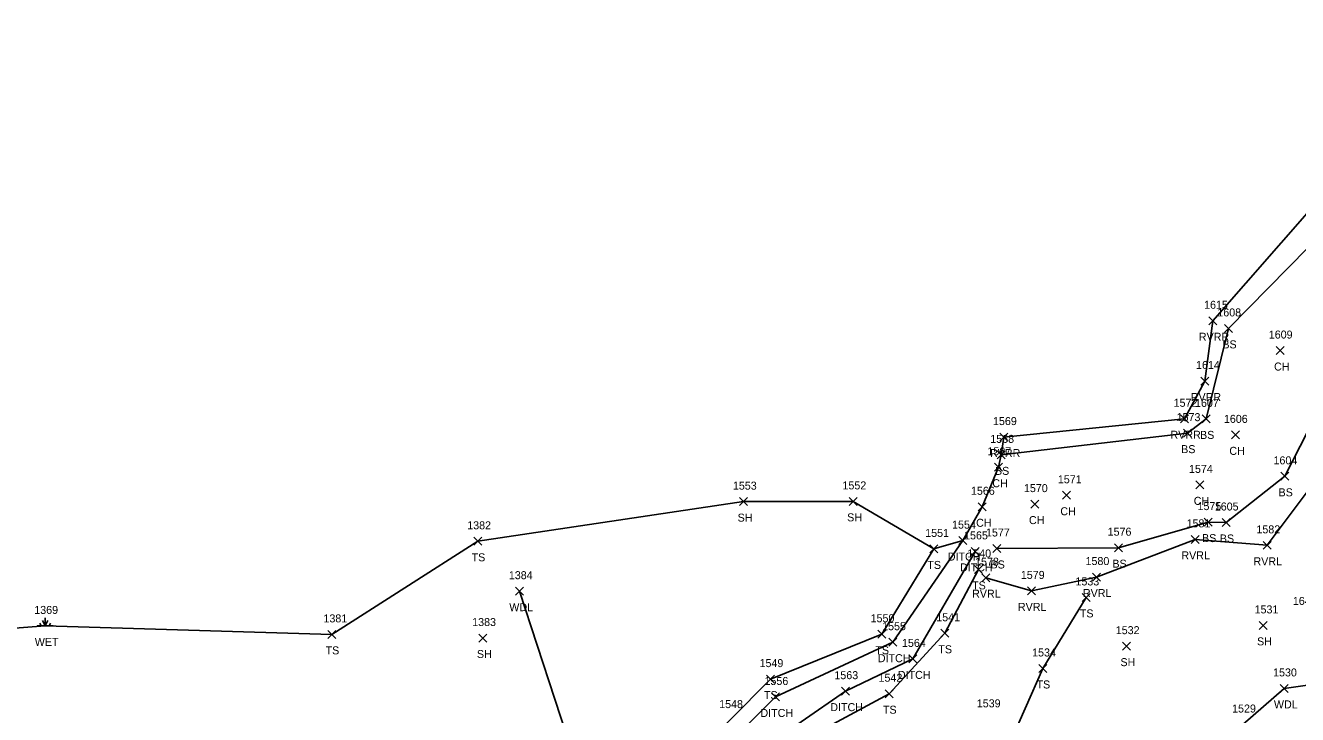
# Model space of a CAD drawing. Extents: x 1633660 to 1636532, y 388643 to 392631.
# Drawn here: x 1633906 to 1634224, y 388875.9 to 389048.3 of the extents above; entities that cross this region are included whole.
import ezdxf

# ---------------------------------------------------------------- set-up
doc = ezdxf.new("R2010")
doc.units = 0
for name, color, linetype in [('D_A', 7, 'Continuous'), ('D_I', 7, 'Continuous'), ('D_TIC', 7, 'Continuous'), ('DD', 7, 'Continuous'), ('L_A', 7, 'Continuous'), ('L_I', 7, 'Continuous'), ('L_TIC', 7, 'Continuous'), ('LAWA', 7, 'Continuous'), ('LAWE', 7, 'Continuous'), ('LELB', 7, 'Continuous'), ('LSOGP', 7, 'Continuous'), ('LWET', 7, 'Continuous')]:
    doc.layers.add(name, color=color, linetype=linetype)

msp = doc.modelspace()

# ---------------------------------------------------------------- linework, layer by layer
at = {"layer": 'D_TIC'}
for points in [[(1634139.31, 388918.4), (1634141.31, 388920.4)], [(1634141.31, 388918.4), (1634139.31, 388920.4)], [(1634142.36, 388915.71), (1634144.36, 388917.71)], [(1634144.36, 388915.71), (1634142.36, 388917.71)], [(1634121.83, 388892.99), (1634123.83, 388894.99)], [(1634123.83, 388892.99), (1634121.83, 388894.99)], [(1634126.84, 388888.81), (1634128.84, 388890.81)], [(1634128.84, 388888.81), (1634126.84, 388890.81)], [(1634109.94, 388880.74), (1634111.94, 388882.74)], [(1634111.94, 388880.74), (1634109.94, 388882.74)], [(1634092.48, 388879.29), (1634094.48, 388881.29)], [(1634094.48, 388879.29), (1634092.48, 388881.29)]]:
    msp.add_lwpolyline(points, dxfattribs=at)
at = {"layer": 'DD'}
msp.add_lwpolyline([(1634140.31, 388919.4), (1634122.83, 388893.99), (1634093.48, 388880.29), (1634083.12, 388870.01), (1634069.93, 388859.42), (1634050.51, 388859.37), (1634048.14, 388856.2), (1634070.58, 388854.91), (1634088.81, 388866.37), (1634110.94, 388881.74), (1634127.84, 388889.81), (1634143.36, 388916.71)], dxfattribs=at)
at = {"layer": 'L_TIC'}
for points in [[(1634201.79, 388973.39), (1634203.79, 388975.39)], [(1634203.79, 388973.39), (1634201.79, 388975.39)], [(1634205.75, 388971.48), (1634207.75, 388973.48)], [(1634207.75, 388971.48), (1634205.75, 388973.48)], [(1634218.62, 388965.94), (1634220.62, 388967.94)], [(1634220.62, 388965.94), (1634218.62, 388967.94)], [(1634199.78, 388958.32), (1634201.78, 388960.32)], [(1634201.78, 388958.32), (1634199.78, 388960.32)], [(1634194.7, 388948.88), (1634196.7, 388950.88)], [(1634196.7, 388948.88), (1634194.7, 388950.88)], [(1634200.17, 388948.84), (1634202.17, 388950.84)], [(1634202.17, 388948.84), (1634200.17, 388950.84)], [(1634149.59, 388944.3), (1634151.59, 388946.3)], [(1634151.59, 388944.3), (1634149.59, 388946.3)], [(1634195.44, 388945.28), (1634197.44, 388947.28)], [(1634197.44, 388945.28), (1634195.44, 388947.28)], [(1634207.44, 388944.85), (1634209.44, 388946.85)], [(1634209.44, 388944.85), (1634207.44, 388946.85)], [(1634148.91, 388939.85), (1634150.91, 388941.85)], [(1634150.91, 388939.85), (1634148.91, 388941.85)], [(1634148.19, 388936.75), (1634150.19, 388938.75)], [(1634150.19, 388936.75), (1634148.19, 388938.75)], [(1634219.78, 388934.48), (1634221.78, 388936.48)], [(1634221.78, 388934.48), (1634219.78, 388936.48)], [(1634198.55, 388932.34), (1634200.55, 388934.34)], [(1634200.55, 388932.34), (1634198.55, 388934.34)], [(1634084.52, 388928.15), (1634086.52, 388930.15)], [(1634086.52, 388928.15), (1634084.52, 388930.15)], [(1634111.91, 388928.21), (1634113.91, 388930.21)], [(1634113.91, 388928.21), (1634111.91, 388930.21)], [(1634165.19, 388929.74), (1634167.19, 388931.74)], [(1634167.19, 388929.74), (1634165.19, 388931.74)], [(1634144.14, 388926.86), (1634146.14, 388928.86)], [(1634146.14, 388926.86), (1634144.14, 388928.86)], [(1634157.35, 388927.53), (1634159.35, 388929.53)], [(1634159.35, 388927.53), (1634157.35, 388929.53)], [(1634200.67, 388923.03), (1634202.67, 388925.03)], [(1634202.67, 388923.03), (1634200.67, 388925.03)], [(1634205.11, 388922.93), (1634207.11, 388924.93)], [(1634207.11, 388922.93), (1634205.11, 388924.93)], [(1634197.37, 388918.71), (1634199.37, 388920.71)], [(1634199.37, 388918.71), (1634197.37, 388920.71)], [(1634018.11, 388918.23), (1634020.11, 388920.23)], [(1634020.11, 388918.23), (1634018.11, 388920.23)], [(1634132.03, 388916.32), (1634134.03, 388918.32)], [(1634134.03, 388916.32), (1634132.03, 388918.32)], [(1634147.79, 388916.43), (1634149.79, 388918.43)], [(1634149.79, 388916.43), (1634147.79, 388918.43)], [(1634178.26, 388916.63), (1634180.26, 388918.63)], [(1634180.26, 388916.63), (1634178.26, 388918.63)], [(1634215.39, 388917.22), (1634217.39, 388919.22)], [(1634217.39, 388917.22), (1634215.39, 388919.22)], [(1634143.21, 388911.2), (1634145.21, 388913.2)], [(1634145.21, 388911.2), (1634143.21, 388913.2)], [(1634145.07, 388909.13), (1634147.07, 388911.13)], [(1634147.07, 388909.13), (1634145.07, 388911.13)], [(1634172.76, 388909.29), (1634174.76, 388911.29)], [(1634174.76, 388909.29), (1634172.76, 388911.29)], [(1634028.51, 388905.75), (1634030.51, 388907.75)], [(1634030.51, 388905.75), (1634028.51, 388907.75)], [(1634156.51, 388905.82), (1634158.51, 388907.82)], [(1634158.51, 388905.82), (1634156.51, 388907.82)], [(1634170.15, 388904.19), (1634172.15, 388906.19)], [(1634172.15, 388904.19), (1634170.15, 388906.19)], [(1634214.37, 388897.19), (1634216.37, 388899.19)], [(1634216.37, 388897.19), (1634214.37, 388899.19)], [(1633981.61, 388894.94), (1633983.61, 388896.94)], [(1633983.61, 388894.94), (1633981.61, 388896.94)], [(1634019.35, 388894.03), (1634021.35, 388896.03)], [(1634021.35, 388894.03), (1634019.35, 388896.03)], [(1634119.03, 388894.98), (1634121.03, 388896.98)], [(1634121.03, 388894.98), (1634119.03, 388896.98)], [(1634134.78, 388895.22), (1634136.78, 388897.22)], [(1634136.78, 388895.22), (1634134.78, 388897.22)], [(1634180.23, 388892), (1634182.23, 388894)], [(1634182.23, 388892), (1634180.23, 388894)], [(1634091.19, 388883.76), (1634093.19, 388885.76)], [(1634093.19, 388883.76), (1634091.19, 388885.76)], [(1634159.33, 388886.42), (1634161.33, 388888.42)], [(1634161.33, 388886.42), (1634159.33, 388888.42)], [(1634219.65, 388881.43), (1634221.65, 388883.43)], [(1634221.65, 388881.43), (1634219.65, 388883.43)], [(1634120.93, 388880.1), (1634122.93, 388882.1)], [(1634122.93, 388880.1), (1634120.93, 388882.1)]]:
    msp.add_lwpolyline(points, dxfattribs=at)
at = {"layer": 'LAWA'}
msp.add_lwpolyline([(1634029.51, 388906.75), (1634042.75, 388866.2), (1634043.29, 388851.86), (1634059.73, 388819.64), (1634086.07, 388831.91), (1634132.5, 388845.49), (1634141.64, 388844.49), (1634171.78, 388858.91), (1634210.32, 388873.4), (1634220.65, 388882.43), (1634241.67, 388885.4), (1634275.37, 388895.77), (1634312.68, 388911.32), (1634346.59, 388927.34), (1634362.7, 388937.8), (1634391.49, 388949.24), (1634419.55, 388956.24), (1634431.93, 388958.02)], dxfattribs=at)
at = {"layer": 'LAWE'}
for points in [[(1634150.59, 388945.3), (1634195.7, 388949.88), (1634200.78, 388959.32), (1634202.79, 388974.39), (1634228.12, 389003.28), (1634254.18, 389019.53), (1634275.87, 389031.31), (1634293.32, 389038.19), (1634304.06, 389038.64), (1634325.39, 389043.75), (1634351.31, 389048.27), (1634372.94, 389046.82), (1634401.07, 389040.69), (1634429.33, 389021.76), (1634441.52, 388999.11), (1634453.12, 388983.42), (1634462.64, 388983.3)], [(1634146.07, 388910.13), (1634157.51, 388906.82), (1634173.76, 388910.29), (1634198.37, 388919.71), (1634216.39, 388918.22), (1634229.12, 388935.26), (1634227.8, 388943.9), (1634246.12, 388965.87), (1634248.24, 388978.32), (1634283.08, 388994.35), (1634319.09, 389007.07), (1634380.98, 389013.99), (1634391.62, 389015.99), (1634409.17, 388992.61), (1634421.79, 388970.69), (1634427.66, 388965.96), (1634434.35, 388960.52)]]:
    msp.add_lwpolyline(points, dxfattribs=at)
at = {"layer": 'LELB'}
for points in [[(1634201.17, 388949.84), (1634206.75, 388972.48), (1634226.62, 388992.7), (1634256.26, 389010.51), (1634290.54, 389028.45), (1634305.7, 389035.69)], [(1634309.1, 389009.74), (1634284.02, 388998.65), (1634245.57, 388982.01), (1634241.27, 388965.71), (1634230.47, 388954.47), (1634220.78, 388935.48), (1634206.11, 388923.93)], [(1634201.17, 388949.84), (1634196.44, 388946.28)], [(1634149.91, 388940.85), (1634196.44, 388946.28)], [(1634201.67, 388924.03), (1634179.26, 388917.63), (1634148.79, 388917.43)], [(1634201.67, 388924.03), (1634206.11, 388923.93)], [(1633982.61, 388895.94), (1634019.11, 388919.23)], [(1634144.21, 388912.2), (1634135.78, 388896.22), (1634121.93, 388881.1), (1634093.91, 388866), (1634071.27, 388853.48), (1634044.09, 388851.99), (1634045.65, 388862.67), (1634068.75, 388861.41), (1634082.09, 388874.51), (1634092.19, 388884.76), (1634120.03, 388895.98), (1634133.03, 388917.32)], [(1634171.15, 388905.19), (1634160.33, 388887.42), (1634151.47, 388867.44), (1634142.01, 388846.15)]]:
    msp.add_lwpolyline(points, dxfattribs=at)
at = {"layer": 'LSOGP'}
msp.add_lwpolyline([(1634228.12, 389003.28), (1634202.79, 388974.39), (1634200.78, 388959.32), (1634195.7, 388949.88), (1634150.59, 388945.3), (1634149.91, 388940.85), (1634149.19, 388937.75), (1634145.14, 388927.86), (1634140.31, 388919.4), (1634133.03, 388917.32), (1634112.91, 388929.21), (1634085.52, 388929.15), (1634019.11, 388919.23), (1633982.61, 388895.94), (1633910.94, 388898.06), (1633887.99, 388896.34)], dxfattribs=at)
at = {"layer": 'LWET'}
for p, q in [((1633909.94, 388898.06), (1633909.61, 388898.73)), ((1633910.94, 388898.06), (1633910.28, 388899.39)), ((1633910.94, 388898.06), (1633910.94, 388900.06)), ((1633910.94, 388898.06), (1633911.61, 388899.39)), ((1633911.94, 388898.06), (1633912.28, 388898.73)), ((1633912.94, 388898.06), (1633908.94, 388898.06))]:
    msp.add_line(p, q, dxfattribs=at)

# ---------------------------------------------------------------- texts
at = {"layer": 'D_A'}
for p in [(1634136.55, 388914.4), (1634139.6, 388911.71), (1634119.06, 388888.99), (1634124.07, 388884.81), (1634089.71, 388875.29), (1634107.18, 388876.74)]:
    msp.add_text('DITCH', height=2, dxfattribs=at).set_placement(p)
at = {"layer": 'D_I'}
for s, p in [('1554', (1634137.62, 388922.4)), ('1565', (1634140.62, 388919.71)), ('1555', (1634120.14, 388896.99)), ('1564', (1634125.1, 388892.81)), ('1563', (1634108.2, 388884.74)), ('1556', (1634090.73, 388883.29))]:
    msp.add_text(s, height=2, dxfattribs=at).set_placement(p)
at = {"layer": 'L_A'}
for s, p in [('RVRR', (1634199.31, 388969.39)), ('BS', (1634205.19, 388967.48)), ('CH', (1634218.11, 388961.94)), ('RVRR', (1634197.29, 388954.32)), ('RVRR', (1634192.21, 388944.88)), ('BS', (1634199.61, 388944.84)), ('BS', (1634194.88, 388941.28)), ('CH', (1634206.93, 388940.85)), ('RVRR', (1634147.11, 388940.3)), ('BS', (1634148.35, 388935.85)), ('CH', (1634147.68, 388932.75)), ('CH', (1634198.04, 388928.34)), ('BS', (1634219.23, 388930.48)), ('CH', (1634164.68, 388925.74)), ('SH', (1634084.01, 388924.15)), ('SH', (1634111.4, 388924.21)), ('CH', (1634143.63, 388922.86)), ('CH', (1634156.84, 388923.53)), ('BS', (1634200.11, 388919.03)), ('BS', (1634204.55, 388918.93)), ('TS', (1634017.52, 388914.23)), ('TS', (1634131.44, 388912.32)), ('BS', (1634147.23, 388912.43)), ('BS', (1634177.7, 388912.63)), ('RVRL', (1634194.94, 388914.71)), ('RVRL', (1634212.96, 388913.22)), ('TS', (1634142.62, 388907.2)), ('RVRL', (1634142.63, 388905.13)), ('RVRL', (1634170.33, 388905.29)), ('WDL', (1634026.93, 388901.75)), ('RVRL', (1634154.08, 388901.82)), ('TS', (1634169.56, 388900.19)), ('WET', (1633908.32, 388893.06)), ('SH', (1634213.85, 388893.19)), ('TS', (1633981.02, 388890.94)), ('SH', (1634018.84, 388890.03)), ('TS', (1634118.44, 388890.98)), ('TS', (1634134.19, 388891.22)), ('SH', (1634179.72, 388888)), ('TS', (1634158.74, 388882.42)), ('TS', (1634090.6, 388879.76)), ('WDL', (1634218.07, 388877.43)), ('TS', (1634120.34, 388876.1))]:
    msp.add_text(s, height=2, dxfattribs=at).set_placement(p)
at = {"layer": 'L_I'}
for s, p in [('1615', (1634200.62, 388977.39)), ('1608', (1634203.93, 388975.48)), ('1609', (1634216.79, 388969.94)), ('1614', (1634198.6, 388962.32)), ('1572', (1634193, 388952.88)), ('1607', (1634198.35, 388952.84)), ('1569', (1634147.85, 388948.3)), ('1573', (1634193.75, 388949.28)), ('1606', (1634205.57, 388948.85)), ('1568', (1634147.17, 388943.85)), ('1567', (1634146.45, 388940.75)), ('1604', (1634217.97, 388938.48)), ('1574', (1634196.85, 388936.34)), ('1553', (1634082.83, 388932.15)), ('1552', (1634110.22, 388932.21)), ('1570', (1634155.58, 388931.53)), ('1571', (1634164.06, 388933.74)), ('1566', (1634142.34, 388930.86)), ('1575', (1634198.97, 388927.03)), ('1605', (1634203.29, 388926.93)), ('1382', (1634016.42, 388922.23)), ('1581', (1634196.24, 388922.71)), ('1551', (1634130.9, 388920.32)), ('1577', (1634146.1, 388920.43)), ('1576', (1634176.51, 388920.63)), ('1582', (1634213.7, 388921.22)), ('1540', (1634141.43, 388915.2)), ('1578', (1634143.37, 388913.13)), ('1580', (1634170.98, 388913.29)), ('1384', (1634026.82, 388909.75)), ('1579', (1634154.81, 388909.82)), ('1533', (1634168.46, 388908.19)), ('1642', (1634222.81, 388903.31)), ('1369', (1633908.19, 388901.06)), ('1531', (1634213.24, 388901.19)), ('1381', (1633980.48, 388898.94)), ('1383', (1634017.66, 388898.03)), ('1550', (1634117.25, 388898.98)), ('1541', (1634133.66, 388899.22)), ('1532', (1634178.54, 388896)), ('1534', (1634157.63, 388890.42)), ('1549', (1634089.49, 388887.76)), ('1542', (1634119.23, 388884.1)), ('1530', (1634217.87, 388885.43)), ('1548', (1634079.4, 388877.51)), ('1539', (1634143.8, 388877.7)), ('1529', (1634207.62, 388876.4))]:
    msp.add_text(s, height=2, dxfattribs=at).set_placement(p)

doc.saveas('drawing.dxf')
